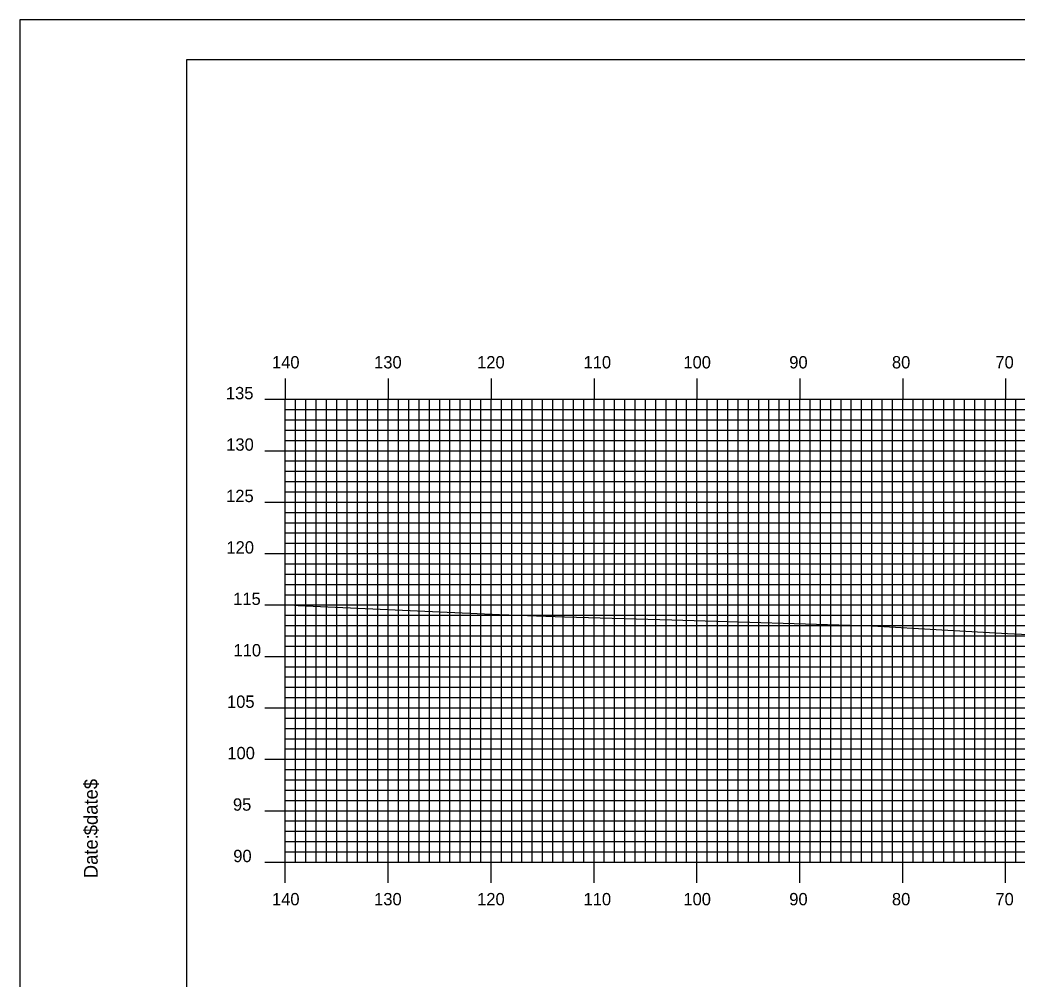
# Model space of a CAD drawing. Extents: x 1785402 to 1785745, y 442591 to 442811.
# Drawn here: x 1785401.8 to 1785498.6, y 442717.3 to 442810.5 of the extents above; entities that cross this region are included whole.
import ezdxf

# ---------------------------------------------------------------- set-up
doc = ezdxf.new("R2010")
doc.units = 0
for name, color, linetype in [('BORDER', 7, 'Continuous'), ('H_V ANNOTATION', 7, 'Continuous'), ('MAJOR', 7, 'Continuous'), ('MINOR', 7, 'Continuous'), ('PLOT BOUNDARY', 7, 'Continuous'), ('S_Roadway_Centerline', 7, 'Continuous')]:
    doc.layers.add(name, color=color, linetype=linetype)

msp = doc.modelspace()

# ---------------------------------------------------------------- linework, layer by layer
at = {"layer": 'BORDER'}
msp.add_lwpolyline([(1785417.939, 442596.665), (1785737.939, 442596.665), (1785737.939, 442806.665), (1785417.939, 442806.665)], close=True, dxfattribs=at)
at = {"layer": 'MAJOR'}
for p, q in [((1785427.539, 442775.669), (1785427.539, 442773.665)), ((1785437.539, 442775.669), (1785437.539, 442773.665)), ((1785447.539, 442775.669), (1785447.539, 442773.665)), ((1785457.539, 442775.669), (1785457.539, 442773.665)), ((1785467.539, 442775.669), (1785467.539, 442773.665)), ((1785477.539, 442775.669), (1785477.539, 442773.665)), ((1785487.539, 442775.669), (1785487.539, 442773.665)), ((1785497.539, 442775.669), (1785497.539, 442773.665)), ((1785425.535, 442773.665), (1785427.539, 442773.665)), ((1785427.539, 442773.665), (1785707.539, 442773.665)), ((1785427.539, 442728.665), (1785427.539, 442773.665)), ((1785427.539, 442728.665), (1785427.539, 442773.665)), ((1785427.539, 442773.665), (1785707.539, 442773.665)), ((1785437.539, 442728.665), (1785437.539, 442773.665)), ((1785447.539, 442728.665), (1785447.539, 442773.665)), ((1785457.539, 442728.665), (1785457.539, 442773.665)), ((1785467.539, 442728.665), (1785467.539, 442773.665)), ((1785477.539, 442728.665), (1785477.539, 442773.665)), ((1785487.539, 442728.665), (1785487.539, 442773.665)), ((1785497.539, 442728.665), (1785497.539, 442773.665)), ((1785425.535, 442768.665), (1785427.539, 442768.665)), ((1785427.539, 442768.665), (1785707.539, 442768.665)), ((1785425.535, 442763.665), (1785427.539, 442763.665)), ((1785427.539, 442763.665), (1785707.539, 442763.665)), ((1785425.535, 442758.665), (1785427.539, 442758.665)), ((1785427.539, 442758.665), (1785707.539, 442758.665)), ((1785425.535, 442753.665), (1785427.539, 442753.665)), ((1785427.539, 442753.665), (1785707.539, 442753.665)), ((1785425.535, 442748.665), (1785427.539, 442748.665)), ((1785427.539, 442748.665), (1785707.539, 442748.665)), ((1785425.535, 442743.665), (1785427.539, 442743.665)), ((1785427.539, 442743.665), (1785707.539, 442743.665)), ((1785425.535, 442738.665), (1785427.539, 442738.665)), ((1785427.539, 442738.665), (1785707.539, 442738.665)), ((1785425.535, 442733.665), (1785427.539, 442733.665)), ((1785427.539, 442733.665), (1785707.539, 442733.665)), ((1785425.535, 442728.665), (1785427.539, 442728.665)), ((1785427.539, 442728.665), (1785707.539, 442728.665)), ((1785427.539, 442728.665), (1785707.539, 442728.665)), ((1785427.539, 442726.661), (1785427.539, 442728.665)), ((1785437.539, 442726.661), (1785437.539, 442728.665)), ((1785447.539, 442726.661), (1785447.539, 442728.665)), ((1785457.539, 442726.661), (1785457.539, 442728.665)), ((1785467.539, 442726.661), (1785467.539, 442728.665)), ((1785477.539, 442726.661), (1785477.539, 442728.665)), ((1785487.539, 442726.661), (1785487.539, 442728.665)), ((1785497.539, 442726.661), (1785497.539, 442728.665))]:
    msp.add_line(p, q, dxfattribs=at)
at = {"layer": 'MINOR'}
for p, q in [((1785428.539, 442728.665), (1785428.539, 442773.665)), ((1785429.539, 442728.665), (1785429.539, 442773.665)), ((1785430.539, 442728.665), (1785430.539, 442773.665)), ((1785431.539, 442728.665), (1785431.539, 442773.665)), ((1785432.539, 442728.665), (1785432.539, 442773.665)), ((1785433.539, 442728.665), (1785433.539, 442773.665)), ((1785434.539, 442728.665), (1785434.539, 442773.665)), ((1785435.539, 442728.665), (1785435.539, 442773.665)), ((1785436.539, 442728.665), (1785436.539, 442773.665)), ((1785438.539, 442728.665), (1785438.539, 442773.665)), ((1785439.539, 442728.665), (1785439.539, 442773.665)), ((1785440.539, 442728.665), (1785440.539, 442773.665)), ((1785441.539, 442728.665), (1785441.539, 442773.665)), ((1785442.539, 442728.665), (1785442.539, 442773.665)), ((1785443.539, 442728.665), (1785443.539, 442773.665)), ((1785444.539, 442728.665), (1785444.539, 442773.665)), ((1785445.539, 442728.665), (1785445.539, 442773.665)), ((1785446.539, 442728.665), (1785446.539, 442773.665)), ((1785448.539, 442728.665), (1785448.539, 442773.665)), ((1785449.539, 442728.665), (1785449.539, 442773.665)), ((1785450.539, 442728.665), (1785450.539, 442773.665)), ((1785451.539, 442728.665), (1785451.539, 442773.665)), ((1785452.539, 442728.665), (1785452.539, 442773.665)), ((1785453.539, 442728.665), (1785453.539, 442773.665)), ((1785454.539, 442728.665), (1785454.539, 442773.665)), ((1785455.539, 442728.665), (1785455.539, 442773.665)), ((1785456.539, 442728.665), (1785456.539, 442773.665)), ((1785458.539, 442728.665), (1785458.539, 442773.665)), ((1785459.539, 442728.665), (1785459.539, 442773.665)), ((1785460.539, 442728.665), (1785460.539, 442773.665)), ((1785461.539, 442728.665), (1785461.539, 442773.665)), ((1785462.539, 442728.665), (1785462.539, 442773.665)), ((1785463.539, 442728.665), (1785463.539, 442773.665)), ((1785464.539, 442728.665), (1785464.539, 442773.665)), ((1785465.539, 442728.665), (1785465.539, 442773.665)), ((1785466.539, 442728.665), (1785466.539, 442773.665)), ((1785468.539, 442728.665), (1785468.539, 442773.665)), ((1785469.539, 442728.665), (1785469.539, 442773.665)), ((1785470.539, 442728.665), (1785470.539, 442773.665)), ((1785471.539, 442728.665), (1785471.539, 442773.665)), ((1785472.539, 442728.665), (1785472.539, 442773.665)), ((1785473.539, 442728.665), (1785473.539, 442773.665)), ((1785474.539, 442728.665), (1785474.539, 442773.665)), ((1785475.539, 442728.665), (1785475.539, 442773.665)), ((1785476.539, 442728.665), (1785476.539, 442773.665)), ((1785478.539, 442728.665), (1785478.539, 442773.665)), ((1785479.539, 442728.665), (1785479.539, 442773.665)), ((1785480.539, 442728.665), (1785480.539, 442773.665)), ((1785481.539, 442728.665), (1785481.539, 442773.665)), ((1785482.539, 442728.665), (1785482.539, 442773.665)), ((1785483.539, 442728.665), (1785483.539, 442773.665)), ((1785484.539, 442728.665), (1785484.539, 442773.665)), ((1785485.539, 442728.665), (1785485.539, 442773.665)), ((1785486.539, 442728.665), (1785486.539, 442773.665)), ((1785488.539, 442728.665), (1785488.539, 442773.665)), ((1785489.539, 442728.665), (1785489.539, 442773.665)), ((1785490.539, 442728.665), (1785490.539, 442773.665)), ((1785491.539, 442728.665), (1785491.539, 442773.665)), ((1785492.539, 442728.665), (1785492.539, 442773.665)), ((1785493.539, 442728.665), (1785493.539, 442773.665)), ((1785494.539, 442728.665), (1785494.539, 442773.665)), ((1785495.539, 442728.665), (1785495.539, 442773.665)), ((1785496.539, 442728.665), (1785496.539, 442773.665)), ((1785498.539, 442728.665), (1785498.539, 442773.665)), ((1785427.539, 442772.665), (1785707.539, 442772.665)), ((1785427.539, 442772.665), (1785429.543, 442772.665)), ((1785427.539, 442771.665), (1785707.539, 442771.665)), ((1785427.539, 442771.665), (1785429.543, 442771.665)), ((1785427.539, 442770.665), (1785707.539, 442770.665)), ((1785427.539, 442770.665), (1785429.543, 442770.665)), ((1785427.539, 442769.665), (1785707.539, 442769.665)), ((1785427.539, 442769.665), (1785429.543, 442769.665)), ((1785427.539, 442767.665), (1785707.539, 442767.665)), ((1785427.539, 442767.665), (1785429.543, 442767.665)), ((1785427.539, 442766.665), (1785707.539, 442766.665)), ((1785427.539, 442766.665), (1785429.543, 442766.665)), ((1785427.539, 442765.665), (1785707.539, 442765.665)), ((1785427.539, 442765.665), (1785429.543, 442765.665)), ((1785427.539, 442764.665), (1785707.539, 442764.665)), ((1785427.539, 442764.665), (1785429.543, 442764.665)), ((1785427.539, 442762.665), (1785707.539, 442762.665)), ((1785427.539, 442762.665), (1785429.543, 442762.665)), ((1785427.539, 442761.665), (1785707.539, 442761.665)), ((1785427.539, 442761.665), (1785429.543, 442761.665)), ((1785427.539, 442760.665), (1785707.539, 442760.665)), ((1785427.539, 442760.665), (1785429.543, 442760.665)), ((1785427.539, 442759.665), (1785707.539, 442759.665)), ((1785427.539, 442759.665), (1785429.543, 442759.665)), ((1785427.539, 442757.665), (1785707.539, 442757.665)), ((1785427.539, 442757.665), (1785429.543, 442757.665)), ((1785427.539, 442756.665), (1785707.539, 442756.665)), ((1785427.539, 442756.665), (1785429.543, 442756.665)), ((1785427.539, 442755.665), (1785707.539, 442755.665)), ((1785427.539, 442755.665), (1785429.543, 442755.665)), ((1785427.539, 442754.665), (1785707.539, 442754.665)), ((1785427.539, 442754.665), (1785429.543, 442754.665)), ((1785427.539, 442752.665), (1785707.539, 442752.665)), ((1785427.539, 442752.665), (1785429.543, 442752.665)), ((1785427.539, 442751.665), (1785707.539, 442751.665)), ((1785427.539, 442751.665), (1785429.543, 442751.665)), ((1785427.539, 442750.665), (1785707.539, 442750.665)), ((1785427.539, 442750.665), (1785429.543, 442750.665)), ((1785427.539, 442749.665), (1785707.539, 442749.665)), ((1785427.539, 442749.665), (1785429.543, 442749.665)), ((1785427.539, 442747.665), (1785707.539, 442747.665)), ((1785427.539, 442747.665), (1785429.543, 442747.665)), ((1785427.539, 442746.665), (1785707.539, 442746.665)), ((1785427.539, 442746.665), (1785429.543, 442746.665)), ((1785427.539, 442745.665), (1785707.539, 442745.665)), ((1785427.539, 442745.665), (1785429.543, 442745.665)), ((1785427.539, 442744.665), (1785707.539, 442744.665)), ((1785427.539, 442744.665), (1785429.543, 442744.665)), ((1785427.539, 442742.665), (1785707.539, 442742.665)), ((1785427.539, 442742.665), (1785429.543, 442742.665)), ((1785427.539, 442741.665), (1785707.539, 442741.665)), ((1785427.539, 442741.665), (1785429.543, 442741.665)), ((1785427.539, 442740.665), (1785707.539, 442740.665)), ((1785427.539, 442740.665), (1785429.543, 442740.665)), ((1785427.539, 442739.665), (1785707.539, 442739.665)), ((1785427.539, 442739.665), (1785429.543, 442739.665)), ((1785427.539, 442737.665), (1785707.539, 442737.665)), ((1785427.539, 442737.665), (1785429.543, 442737.665)), ((1785427.539, 442736.665), (1785707.539, 442736.665)), ((1785427.539, 442736.665), (1785429.543, 442736.665)), ((1785427.539, 442735.665), (1785707.539, 442735.665)), ((1785427.539, 442735.665), (1785429.543, 442735.665)), ((1785427.539, 442734.665), (1785707.539, 442734.665)), ((1785427.539, 442734.665), (1785429.543, 442734.665)), ((1785427.539, 442732.665), (1785707.539, 442732.665)), ((1785427.539, 442732.665), (1785429.543, 442732.665)), ((1785427.539, 442731.665), (1785707.539, 442731.665)), ((1785427.539, 442731.665), (1785429.543, 442731.665)), ((1785427.539, 442730.665), (1785707.539, 442730.665)), ((1785427.539, 442730.665), (1785429.543, 442730.665)), ((1785427.539, 442729.665), (1785707.539, 442729.665)), ((1785427.539, 442729.665), (1785429.543, 442729.665))]:
    msp.add_line(p, q, dxfattribs=at)
at = {"layer": 'PLOT BOUNDARY'}
msp.add_lwpolyline([(1785401.752, 442590.547), (1785741.752, 442590.547), (1785741.752, 442810.547), (1785401.752, 442810.547)], close=True, dxfattribs=at)
at = {"layer": 'S_Roadway_Centerline'}
msp.add_lwpolyline([(1785427.539, 442753.725), (1785428.429, 442753.654), (1785428.797, 442753.631), (1785448.35, 442752.725), (1785454.674, 442752.52), (1785465.099, 442752.208), (1785484.556, 442751.635), (1785491.348, 442751.24), (1785497.706, 442750.905), (1785506.575, 442750.469)], dxfattribs=at)

# ---------------------------------------------------------------- texts
at = {"layer": 'BORDER'}
for s, p in [('$date$', (1785409.308, 442731.275)), ('$date$', (1785409.308, 442731.275)), ('Date:', (1785409.308, 442727.099)), ('Date:', (1785409.308, 442727.099))]:
    msp.add_text(s, height=1.3392, rotation=90, dxfattribs=at).set_placement(p)
at = {"layer": 'H_V ANNOTATION'}
for s, p in [('140', (1785426.244, 442776.665)), ('130', (1785436.169, 442776.665)), ('120', (1785446.179, 442776.665)), ('110', (1785456.522, 442776.665)), ('100', (1785466.222, 442776.665)), ('90', (1785476.511, 442776.665)), ('80', (1785486.489, 442776.665)), ('70', (1785496.543, 442776.665)), ('135', (1785421.766, 442773.665)), ('130', (1785421.798, 442768.665)), ('125', (1785421.788, 442763.665)), ('120', (1785421.82, 442758.665)), ('115', (1785422.473, 442753.665)), ('110', (1785422.505, 442748.665)), ('105', (1785421.873, 442743.665)), ('100', (1785421.905, 442738.665)), ('95', (1785422.451, 442733.665)), ('90', (1785422.483, 442728.665)), ('140', (1785426.244, 442724.465)), ('130', (1785436.169, 442724.465)), ('120', (1785446.179, 442724.465)), ('110', (1785456.522, 442724.465)), ('100', (1785466.222, 442724.465)), ('90', (1785476.511, 442724.465)), ('80', (1785486.489, 442724.465)), ('70', (1785496.543, 442724.465))]:
    msp.add_text(s, height=1.2, dxfattribs=at).set_placement(p)
at = {"layer": 'MAJOR'}
msp.add_text('-', height=0.012, dxfattribs=at).set_placement((1785427.53, 442728.665))

doc.saveas('drawing.dxf')
